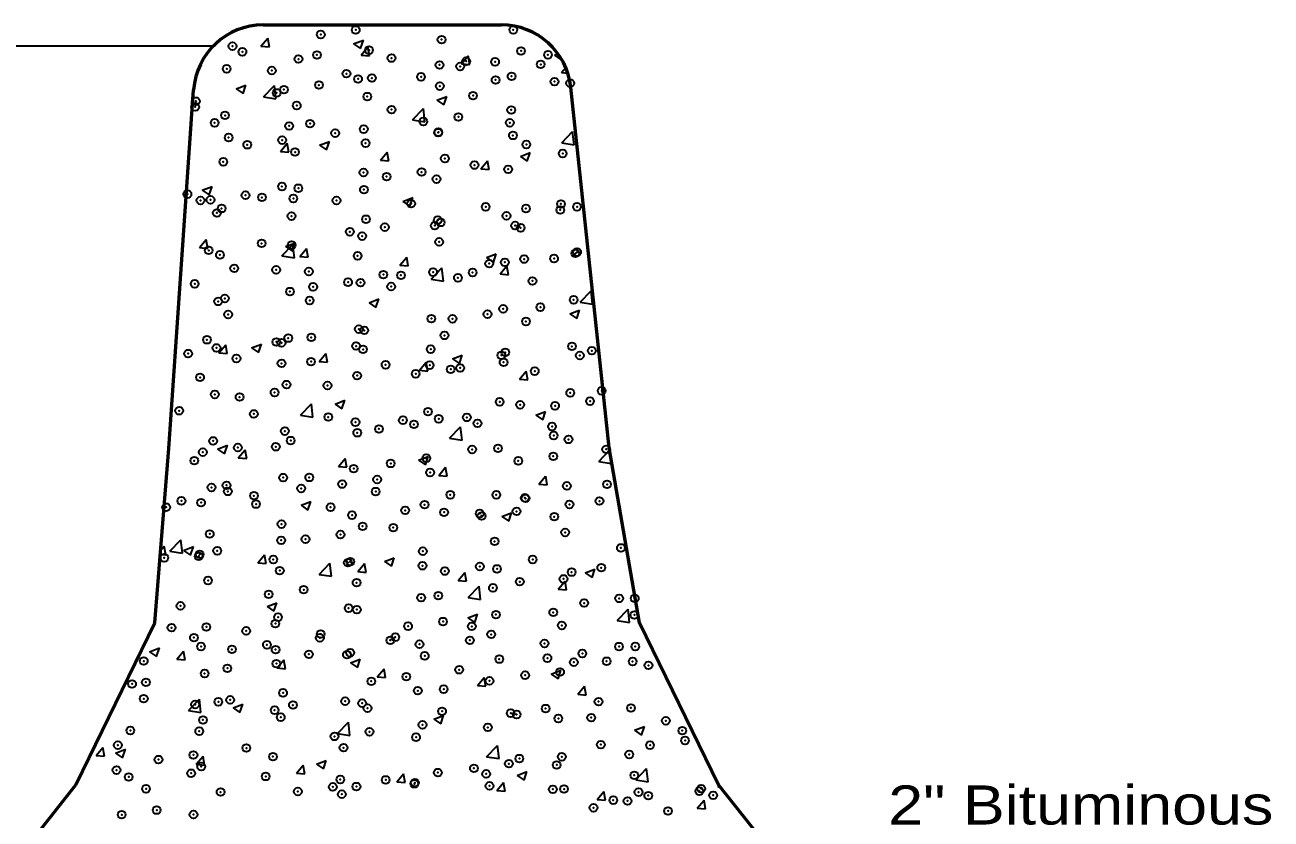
# Model space of a CAD drawing. Extents: x 14 to 49.3, y 28 to 50.
# Drawn here: x 34.953 to 39.413, y 38.182 to 41.024 of the extents above; entities that cross this region are included whole.
import ezdxf

# ---------------------------------------------------------------- set-up
doc = ezdxf.new("R2010")
doc.units = 0
doc.header["$LTSCALE"] = 0.056
doc.header["$PDMODE"] = 32
doc.header["$PDSIZE"] = 0.028
for name, color, linetype, lineweight in [('1', 7, 'Continuous', 35), ('3', 7, 'Continuous', 13), ('6', 7, 'Continuous', 13)]:
    doc.layers.add(name, color=color, linetype=linetype, lineweight=lineweight)

msp = doc.modelspace()

# ---------------------------------------------------------------- linework, layer by layer
at = {"layer": '1', "lineweight": 53}
for p, q in [((35.80625, 41.02392), (36.65817, 41.02392)), ((35.46842, 39.50783), (35.55683, 40.79108)), ((35.41742, 38.88442), (35.46842, 39.50783)), ((35.13542, 38.30408), (35.41742, 38.88442)), ((34.53892, 37.553), (35.13542, 38.30408))]:
    msp.add_line(p, q, dxfattribs=at)
at = {"layer": '1'}
for p, q in [((35.63342, 40.94792), (32.45458, 40.94792)), ((35.79783, 40.94767), (35.82192, 40.97633)), ((35.79783, 40.94767), (35.82775, 40.945)), ((35.82775, 40.945), (35.82192, 40.97633)), ((36.12933, 40.95617), (36.16433, 40.96967)), ((36.12933, 40.95617), (36.15417, 40.93942)), ((36.15417, 40.93942), (36.16433, 40.96958)), ((36.1565, 40.91625), (36.18058, 40.945)), ((36.18633, 40.91358), (36.18058, 40.945)), ((36.1565, 40.91625), (36.18633, 40.91367)), ((36.51508, 40.88483), (36.53917, 40.91358)), ((36.545, 40.88225), (36.53925, 40.91358)), ((36.84783, 40.91617), (36.86033, 40.92092)), ((36.84783, 40.91617), (36.87275, 40.89942)), ((36.87275, 40.89933), (36.87333, 40.90117)), ((36.51508, 40.88483), (36.545, 40.88225)), ((36.87375, 40.8535), (36.8885, 40.87108)), ((36.87375, 40.8535), (36.89575, 40.85158)), ((35.70917, 40.79492), (35.74417, 40.80833)), ((35.70917, 40.79492), (35.73408, 40.77817)), ((35.73408, 40.77817), (35.74417, 40.80833)), ((35.80675, 40.76692), (35.84567, 40.8075)), ((35.80675, 40.76692), (35.85117, 40.76)), ((35.85125, 40.76), (35.84567, 40.8075)), ((36.42775, 40.75492), (36.46275, 40.76833)), ((36.45267, 40.73808), (36.46275, 40.76833)), ((36.34033, 40.68417), (36.37933, 40.72475)), ((36.38483, 40.67725), (36.37933, 40.72475)), ((36.42775, 40.75492), (36.45258, 40.73808)), ((36.34033, 40.68417), (36.38483, 40.67725)), ((36.874, 40.60142), (36.91292, 40.642)), ((36.91842, 40.5945), (36.91292, 40.642)), ((35.86725, 40.5715), (35.89133, 40.60025)), ((35.89708, 40.56892), (35.89133, 40.60025)), ((36.00767, 40.59358), (36.04267, 40.60708)), ((36.00767, 40.59358), (36.0325, 40.57683)), ((36.0325, 40.57683), (36.04267, 40.60708)), ((36.874, 40.60142), (36.91842, 40.5945)), ((35.86725, 40.5715), (35.89708, 40.56892)), ((36.22583, 40.54017), (36.24992, 40.56892)), ((36.25575, 40.5375), (36.24992, 40.56883)), ((36.72617, 40.55358), (36.76125, 40.567)), ((36.72617, 40.55358), (36.75108, 40.53683)), ((36.75108, 40.53675), (36.76125, 40.567)), ((36.22583, 40.54017), (36.25575, 40.5375)), ((36.5845, 40.50875), (36.60858, 40.5375)), ((36.5845, 40.50875), (36.61433, 40.50617)), ((36.61433, 40.50617), (36.60858, 40.5375)), ((35.5875, 40.43233), (35.6225, 40.44583)), ((35.5875, 40.43233), (35.61242, 40.41558)), ((35.61242, 40.41558), (35.62258, 40.44575)), ((36.30608, 40.39233), (36.34108, 40.40575)), ((36.30608, 40.39233), (36.331, 40.3755)), ((36.331, 40.3755), (36.34108, 40.40575)), ((35.57792, 40.22683), (35.60208, 40.2555)), ((35.60783, 40.22417), (35.60208, 40.2555)), ((35.873, 40.19708), (35.912, 40.23767)), ((35.886, 40.23108), (35.921, 40.2445)), ((35.886, 40.23108), (35.91083, 40.21425)), ((35.91083, 40.21425), (35.921, 40.2445)), ((35.9175, 40.19017), (35.912, 40.23767)), ((35.57792, 40.22683), (35.60783, 40.22417)), ((35.873, 40.19708), (35.9175, 40.19017)), ((35.93658, 40.19542), (35.96067, 40.22417)), ((35.93658, 40.19542), (35.9665, 40.19283)), ((35.9665, 40.19283), (35.96067, 40.22417)), ((36.29525, 40.16408), (36.31933, 40.19275)), ((36.32508, 40.16142), (36.31933, 40.19275)), ((36.60458, 40.191), (36.63958, 40.20442)), ((36.60458, 40.191), (36.62942, 40.17425)), ((36.62942, 40.17417), (36.63958, 40.20442)), ((36.29525, 40.16408), (36.32508, 40.16142)), ((36.40667, 40.11433), (36.44558, 40.15492)), ((36.45108, 40.10742), (36.44558, 40.15492)), ((36.65383, 40.13267), (36.67792, 40.16142)), ((36.68375, 40.13008), (36.678, 40.16142)), ((36.40667, 40.11433), (36.45108, 40.10742)), ((36.65383, 40.13267), (36.68375, 40.13008)), ((36.94025, 40.03158), (36.97917, 40.07217)), ((36.98475, 40.02467), (36.97925, 40.07217)), ((36.18442, 40.02975), (36.21942, 40.04317)), ((36.18442, 40.02975), (36.20933, 40.013)), ((36.20933, 40.01292), (36.21942, 40.04317)), ((36.94025, 40.03158), (36.98475, 40.02467)), ((36.903, 39.98967), (36.938, 40.00317)), ((36.903, 39.98967), (36.92783, 39.97292)), ((36.92792, 39.97292), (36.938, 40.00308)), ((35.64733, 39.85075), (35.67142, 39.87942)), ((35.67725, 39.84808), (35.67142, 39.87942)), ((35.76433, 39.8685), (35.79933, 39.88192)), ((35.78917, 39.85167), (35.79933, 39.88192)), ((35.64733, 39.85075), (35.67725, 39.84808)), ((35.76433, 39.8685), (35.78917, 39.85167)), ((36.006, 39.81933), (36.03008, 39.84808)), ((36.03583, 39.81667), (36.03008, 39.84808)), ((36.48292, 39.82842), (36.51792, 39.84183)), ((36.50775, 39.81167), (36.51792, 39.84183)), ((36.006, 39.81933), (36.03583, 39.81675)), ((36.36458, 39.788), (36.38867, 39.81667)), ((36.36458, 39.788), (36.3945, 39.78533)), ((36.3945, 39.78533), (36.38867, 39.81667)), ((36.48292, 39.82842), (36.50775, 39.81167)), ((36.72325, 39.75658), (36.74733, 39.78533)), ((36.75308, 39.75392), (36.74733, 39.78533)), ((36.72325, 39.75658), (36.75308, 39.754)), ((35.93933, 39.62725), (35.97825, 39.66783)), ((35.98375, 39.62033), (35.97825, 39.66783)), ((36.06275, 39.66717), (36.09775, 39.68058)), ((36.06275, 39.66717), (36.08767, 39.65042)), ((36.08767, 39.65033), (36.09783, 39.68058)), ((35.93933, 39.62725), (35.98375, 39.62042)), ((36.78133, 39.62708), (36.81633, 39.64058)), ((36.78133, 39.62708), (36.80625, 39.61033)), ((36.80625, 39.61033), (36.81633, 39.6405)), ((36.47292, 39.5445), (36.51192, 39.58508)), ((36.51742, 39.53758), (36.51192, 39.58508)), ((36.51742, 39.53758), (36.51192, 39.58508)), ((35.64267, 39.50592), (35.67767, 39.51933)), ((35.66758, 39.48908), (35.67767, 39.51933)), ((36.47292, 39.5445), (36.51742, 39.53758)), ((35.64267, 39.50592), (35.6675, 39.48908)), ((35.71667, 39.47458), (35.74083, 39.50333)), ((35.71667, 39.47458), (35.74658, 39.472)), ((35.74658, 39.472), (35.74083, 39.50333)), ((36.36125, 39.46583), (36.39625, 39.47925)), ((36.38608, 39.44908), (36.39625, 39.47925)), ((37.00658, 39.46175), (37.0455, 39.50233)), ((37.051, 39.45483), (37.0455, 39.50233)), ((36.07533, 39.44325), (36.09942, 39.472)), ((36.07533, 39.44325), (36.10525, 39.44067)), ((36.07533, 39.44325), (36.10525, 39.44067)), ((36.10525, 39.44058), (36.09942, 39.47192)), ((36.36125, 39.46583), (36.38608, 39.44908)), ((36.434, 39.41183), (36.45808, 39.44058)), ((36.46383, 39.40925), (36.45808, 39.44058)), ((37.00658, 39.46175), (37.051, 39.45483)), ((36.434, 39.41183), (36.46383, 39.40925)), ((36.79258, 39.3805), (36.81667, 39.40925)), ((36.8225, 39.37783), (36.81675, 39.40917)), ((36.8225, 39.37783), (36.81675, 39.40917)), ((36.79258, 39.3805), (36.8225, 39.37783)), ((35.94108, 39.30458), (35.97617, 39.318)), ((35.94108, 39.30458), (35.966, 39.28783)), ((35.966, 39.28783), (35.97617, 39.318)), ((36.65967, 39.26458), (36.69467, 39.278)), ((36.65967, 39.26458), (36.68458, 39.24775)), ((36.68458, 39.24775), (36.69467, 39.278)), ((35.472, 39.14025), (35.51092, 39.18083)), ((35.51642, 39.13333), (35.51092, 39.18083)), ((35.43742, 39.129), (35.45733, 39.12725)), ((35.43858, 39.14317), (35.45158, 39.15858)), ((35.45733, 39.12725), (35.45158, 39.15858)), ((35.472, 39.14025), (35.51642, 39.13333)), ((35.521, 39.14333), (35.556, 39.15675)), ((35.521, 39.14333), (35.54592, 39.12658)), ((35.54592, 39.1265), (35.556, 39.15675)), ((35.78608, 39.0985), (35.81017, 39.12725)), ((35.816, 39.09592), (35.81017, 39.12725)), ((36.23958, 39.10325), (36.27458, 39.11675)), ((36.26442, 39.0865), (36.27458, 39.11667)), ((35.78608, 39.0985), (35.816, 39.09592)), ((36.00558, 39.0575), (36.04458, 39.09808)), ((36.05008, 39.05058), (36.04458, 39.098)), ((36.14475, 39.06717), (36.16883, 39.09583)), ((36.17458, 39.0645), (36.16883, 39.09583)), ((36.23958, 39.10325), (36.26442, 39.0865)), ((36.95817, 39.06325), (36.99317, 39.07667)), ((36.983, 39.04642), (36.99317, 39.07667)), ((36.00558, 39.0575), (36.05008, 39.05058)), ((36.14475, 39.06717), (36.17458, 39.0645)), ((36.50333, 39.03575), (36.52742, 39.0645)), ((36.50333, 39.03575), (36.53325, 39.03317)), ((36.53325, 39.03317), (36.52742, 39.0645)), ((36.862, 39.00442), (36.88608, 39.03308)), ((36.89183, 39.00175), (36.88608, 39.03308)), ((36.95817, 39.06325), (36.983, 39.04642)), ((36.53925, 38.97467), (36.57817, 39.01525)), ((36.58367, 38.96775), (36.57817, 39.01525)), ((36.862, 39.00442), (36.89183, 39.00175)), ((35.8195, 38.942), (35.8545, 38.95542)), ((35.8195, 38.942), (35.84433, 38.92525)), ((35.84433, 38.92525), (35.8545, 38.95542)), ((36.53925, 38.97467), (36.58367, 38.96783)), ((36.538, 38.902), (36.573, 38.91542)), ((36.538, 38.902), (36.56292, 38.88517)), ((36.56292, 38.88517), (36.57308, 38.91542)), ((37.07283, 38.89192), (37.11175, 38.9325)), ((37.11733, 38.885), (37.11183, 38.9325)), ((37.07283, 38.89192), (37.11733, 38.88508)), ((35.39933, 38.78075), (35.43433, 38.79417)), ((35.39933, 38.78075), (35.42425, 38.764)), ((35.39933, 38.78075), (35.42425, 38.764)), ((35.42425, 38.76392), (35.43433, 38.79417)), ((35.49683, 38.75383), (35.52092, 38.7825)), ((35.52675, 38.75117), (35.52092, 38.7825)), ((35.49683, 38.75383), (35.52675, 38.75117)), ((35.85542, 38.72242), (35.87958, 38.75117)), ((35.85542, 38.72242), (35.88533, 38.71983)), ((35.88533, 38.71983), (35.87958, 38.75117)), ((36.11792, 38.74067), (36.15292, 38.75417)), ((36.11792, 38.74067), (36.14275, 38.72392)), ((36.14283, 38.72392), (36.15292, 38.75408)), ((36.21408, 38.69108), (36.23817, 38.71975)), ((36.244, 38.68842), (36.23817, 38.71975)), ((36.8365, 38.70067), (36.8715, 38.71408)), ((36.86133, 38.68383), (36.8715, 38.71408)), ((36.21408, 38.69108), (36.244, 38.68842)), ((36.57275, 38.65967), (36.59683, 38.68842)), ((36.60258, 38.657), (36.59683, 38.68842)), ((36.8365, 38.70067), (36.86133, 38.68392)), ((36.57275, 38.65967), (36.60258, 38.65708)), ((36.93133, 38.62833), (36.95542, 38.657)), ((36.93133, 38.62833), (36.96125, 38.62567)), ((36.96125, 38.62567), (36.9555, 38.657)), ((35.53825, 38.57042), (35.57725, 38.611)), ((35.58275, 38.5635), (35.57725, 38.611)), ((35.69783, 38.57942), (35.73283, 38.59283)), ((35.72267, 38.56267), (35.73283, 38.59283)), ((37.29, 38.59692), (37.29167, 38.59892)), ((37.29, 38.59692), (37.29275, 38.59667)), ((35.53825, 38.57042), (35.58275, 38.5635)), ((35.69783, 38.57942), (35.72267, 38.56267)), ((36.41633, 38.53942), (36.45142, 38.55283)), ((36.41633, 38.53942), (36.44125, 38.52258)), ((36.44125, 38.52258), (36.45142, 38.55283)), ((36.07192, 38.48767), (36.11083, 38.52825)), ((36.11633, 38.48075), (36.11083, 38.52825)), ((37.13492, 38.49933), (37.16992, 38.51275)), ((37.13492, 38.49933), (37.15983, 38.48258)), ((37.15983, 38.48258), (37.16992, 38.51275)), ((36.07192, 38.48767), (36.11633, 38.48075)), ((35.20758, 38.40908), (35.23167, 38.43783)), ((35.20758, 38.40908), (35.2375, 38.4065)), ((35.2375, 38.40642), (35.23167, 38.43775)), ((35.27767, 38.41817), (35.31267, 38.43158)), ((35.27767, 38.41817), (35.30258, 38.40142)), ((35.30258, 38.40142), (35.31275, 38.43158)), ((35.56617, 38.37767), (35.59033, 38.40642)), ((35.59608, 38.37508), (35.59033, 38.40642)), ((36.6055, 38.40492), (36.64442, 38.4455)), ((36.6055, 38.40492), (36.65, 38.398)), ((36.65, 38.398), (36.6445, 38.44542)), ((35.56617, 38.37767), (35.59608, 38.37508)), ((35.92483, 38.34633), (35.94892, 38.37508)), ((35.95475, 38.34367), (35.94892, 38.375)), ((35.99625, 38.37817), (36.03125, 38.39158)), ((35.99625, 38.37817), (36.02117, 38.36133)), ((36.02117, 38.36133), (36.03125, 38.39158)), ((37.13917, 38.32208), (37.17808, 38.36275)), ((37.18358, 38.31525), (37.17808, 38.36267)), ((35.92483, 38.34633), (35.95475, 38.34375)), ((36.2835, 38.31492), (36.30758, 38.34367)), ((36.2835, 38.31492), (36.31333, 38.31233)), ((36.31333, 38.31233), (36.30758, 38.34367)), ((36.71483, 38.33808), (36.74983, 38.3515)), ((36.71483, 38.33808), (36.73967, 38.32133)), ((36.73967, 38.32125), (36.74983, 38.3515)), ((37.13917, 38.32208), (37.18358, 38.31525)), ((36.64208, 38.28358), (36.66617, 38.31233)), ((36.64208, 38.28358), (36.672, 38.281)), ((36.672, 38.28092), (36.66617, 38.31225)), ((37.00075, 38.25217), (37.02483, 38.28092)), ((37.03058, 38.24958), (37.02483, 38.28092)), ((37.43342, 38.298), (37.43825, 38.29992)), ((37.43342, 38.298), (37.447, 38.28883)), ((37.00075, 38.25217), (37.03058, 38.24958)), ((37.35933, 38.22083), (37.38342, 38.24958)), ((37.38925, 38.21817), (37.3835, 38.2495)), ((37.35933, 38.22083), (37.38925, 38.21825))]:
    msp.add_line(p, q, dxfattribs=at)
at = {"layer": '1', "lineweight": 53}
msp.add_lwpolyline([(38.0315, 37.553), (37.43492, 38.30408), (37.15292, 38.88442), (37.04442, 39.51033), (36.90675, 40.80042)], dxfattribs=at)
for centre, start, end in [((35.80625, 40.77392), 90, 176.0601), ((36.65817, 40.77392), 6.09322, 90)]:
    msp.add_arc(centre, 0.25, start, end, dxfattribs=at)
at = {"layer": '1'}
for p in [(36.01175, 40.9895), (36.13692, 41.006), (36.70083, 41.0065), (35.69592, 40.94792), (36.18442, 40.93383), (36.44417, 40.97133), (36.7285, 40.93075), (35.73133, 40.92783), (35.93192, 40.90183), (35.99825, 40.9165), (36.26517, 40.90525), (36.532, 40.894), (36.63567, 40.89175), (36.825, 40.91675), (35.67517, 40.86658), (35.83675, 40.86067), (36.10367, 40.84933), (36.43692, 40.88067), (36.5105, 40.87533), (36.79892, 40.88267), (36.00533, 40.80883), (36.14533, 40.83058), (36.19475, 40.83375), (36.37058, 40.83808), (36.43808, 40.80492), (36.6375, 40.82683), (36.69475, 40.84008), (36.84833, 40.82092), (36.90433, 40.8155), (35.85375, 40.78058), (35.88017, 40.79233), (36.17833, 40.76742), (36.55675, 40.77092), (35.56217, 40.7305), (35.56442, 40.75075), (35.92583, 40.73542), (36.26517, 40.72083), (36.6935, 40.7195), (35.63183, 40.67367), (35.66908, 40.70017), (35.97358, 40.67075), (36.379, 40.67808), (36.50417, 40.69458), (36.68867, 40.67367), (35.682, 40.62075), (35.89875, 40.66233), (36.06317, 40.6365), (36.16567, 40.65108), (36.432, 40.63842), (36.43258, 40.63983), (36.6995, 40.6285), (35.74867, 40.59508), (35.87383, 40.61158), (36.17225, 40.60092), (36.74767, 40.59592), (35.663, 40.53375), (35.91975, 40.56892), (36.45608, 40.54583), (36.87775, 40.56383), (36.1645, 40.49583), (36.37258, 40.49733), (36.562, 40.52233), (36.68258, 40.50717), (35.87292, 40.44575), (36.24742, 40.48092), (36.42592, 40.472), (35.5345, 40.41817), (35.58133, 40.39567), (35.61708, 40.39792), (35.74225, 40.41442), (35.80133, 40.40683), (35.91367, 40.4025), (35.93167, 40.43933), (36.06825, 40.39558), (36.16625, 40.4345), (35.63992, 40.351), (35.65692, 40.36725), (36.33517, 40.38433), (36.60208, 40.373), (36.74617, 40.36667), (36.869, 40.36175), (36.87142, 40.38317), (36.92908, 40.37275), (35.90683, 40.33967), (36.17367, 40.32842), (36.43042, 40.32508), (36.44058, 40.31717), (36.67658, 40.34075), (36.7075, 40.30583), (36.11592, 40.28367), (36.16017, 40.26808), (36.24108, 40.30017), (36.41983, 40.3055), (36.72708, 40.29758), (35.61075, 40.21717), (35.80008, 40.24208), (35.90758, 40.236), (36.4355, 40.2475), (35.65083, 40.20083), (36.14383, 40.1975), (36.6705, 40.17433), (36.73983, 40.18592), (36.84683, 40.18783), (36.923, 40.20633), (36.92917, 40.21083), (35.70192, 40.15275), (35.85225, 40.14742), (35.96883, 40.14142), (36.23575, 40.13017), (36.29892, 40.12792), (36.41375, 40.13908), (36.55525, 40.13775), (36.61467, 40.1695), (35.56067, 40.09733), (35.98433, 40.0865), (36.1095, 40.103), (36.15408, 40.10158), (36.26367, 40.08767), (36.50267, 40.11892), (36.7695, 40.10758), (35.66858, 40.04492), (35.9015, 40.06958), (36.91692, 40.03983), (35.64475, 40.03442), (35.97208, 40.03767), (36.66442, 40.00783), (36.79767, 40.01367), (35.6805, 39.98758), (36.40767, 39.97267), (36.48317, 39.97225), (36.60833, 39.98875), (36.74625, 39.96275), (35.978, 39.90575), (36.148, 39.93517), (36.16733, 39.93067), (36.45467, 39.91275), (35.6045, 39.89725), (35.63867, 39.86792), (35.85283, 39.88925), (35.87142, 39.88592), (35.89542, 39.90317), (36.13833, 39.87467), (36.163, 39.86267), (36.40525, 39.86342), (36.91083, 39.87342), (35.53708, 39.84767), (35.70992, 39.83008), (35.97683, 39.81875), (36.65833, 39.84142), (36.66617, 39.8165), (36.67217, 39.85208), (36.93908, 39.84083), (36.98192, 39.858), (35.87142, 39.81258), (36.24375, 39.8075), (36.35158, 39.77508), (36.40158, 39.80617), (36.47675, 39.7915), (36.51067, 39.79625), (36.77758, 39.78492), (35.57983, 39.76258), (35.88933, 39.73667), (36.03583, 39.7335), (36.14192, 39.76875), (35.63258, 39.7015), (35.72125, 39.69208), (35.8465, 39.70858), (36.90475, 39.707), (37.01717, 39.7145), (35.50508, 39.64308), (36.3955, 39.63975), (36.65225, 39.67492), (36.72558, 39.66442), (36.85042, 39.66083), (36.97558, 39.67733), (35.772, 39.63175), (36.03883, 39.6205), (36.13583, 39.60225), (36.30575, 39.60925), (36.34525, 39.59433), (36.434, 39.61442), (36.53458, 39.61925), (36.57267, 39.59792), (35.88325, 39.57025), (36.14242, 39.56433), (36.22008, 39.57783), (36.83958, 39.58667), (36.84542, 39.55467), (35.6265, 39.53508), (35.71492, 39.51133), (35.85083, 39.51425), (35.90425, 39.53625), (36.55383, 39.50458), (36.64617, 39.5085), (36.89867, 39.5405), (37.03342, 39.505), (35.55925, 39.46425), (35.58975, 39.49483), (36.38942, 39.47333), (36.71883, 39.46358), (36.844, 39.48008), (36.12975, 39.43583), (36.26217, 39.45458), (36.40308, 39.42208), (35.67458, 39.37625), (35.87717, 39.40383), (35.97058, 39.4045), (36.0885, 39.38067), (36.21367, 39.39708), (36.89258, 39.37408), (37.03633, 39.37967), (35.6205, 39.36858), (35.679, 39.35442), (35.77275, 39.33908), (35.9415, 39.365), (36.20842, 39.35375), (36.47533, 39.34242), (36.64008, 39.34208), (36.74225, 39.33117), (36.74475, 39.32958), (35.45825, 39.29767), (35.51308, 39.32042), (35.58342, 39.31417), (35.78, 39.30908), (36.04692, 39.29783), (36.31383, 39.28658), (36.38333, 39.30683), (36.7125, 39.28292), (36.90183, 39.30783), (37.00917, 39.31992), (35.87108, 39.23733), (36.12367, 39.26933), (36.45317, 39.27958), (36.58075, 39.27525), (36.58733, 39.26642), (36.84767, 39.264), (35.61442, 39.20217), (36.08217, 39.19992), (36.16158, 39.2295), (36.2715, 39.22483), (36.8865, 39.20758), (35.87, 39.1795), (35.957, 39.18342), (36.634, 39.17558), (37.08608, 39.15217), (35.45183, 39.11692), (35.57508, 39.12217), (35.57842, 39.12942), (35.64125, 39.14183), (35.842, 39.11083), (36.11758, 39.10292), (36.37725, 39.14042), (36.77033, 39.11058), (35.865, 39.07092), (36.10892, 39.09958), (36.37583, 39.08833), (36.45575, 39.06925), (36.58092, 39.08567), (36.64275, 39.077), (36.90967, 39.06575), (37.01567, 39.08133), (35.60833, 39.03567), (36.14, 39.02767), (36.72408, 39.03133), (36.88042, 39.04117), (35.8255, 38.98625), (35.95067, 39.00267), (36.37117, 38.974), (36.4325, 38.98125), (36.62792, 39.00917), (37.07975, 38.9715), (37.1355, 38.97158), (35.50967, 38.94467), (36.1115, 38.9365), (36.14092, 38.93117), (36.95458, 38.955), (35.84933, 38.88117), (35.85892, 38.9045), (36.44942, 38.8885), (36.63875, 38.91342), (36.84392, 38.9215), (37.13408, 38.91225), (35.47775, 38.86667), (35.60225, 38.86925), (35.74467, 38.85533), (36.01158, 38.84408), (36.32425, 38.872), (36.55233, 38.87142), (36.62183, 38.84275), (36.87442, 38.87475), (35.55775, 38.83108), (35.58317, 38.7995), (35.81908, 38.8055), (36.0085, 38.83042), (36.26075, 38.82142), (36.2785, 38.83283), (36.36508, 38.8075), (36.54542, 38.8215), (36.81233, 38.81025), (37.07925, 38.799), (37.13758, 38.79917), (35.37817, 38.74742), (35.69392, 38.789), (35.85008, 38.78817), (35.96917, 38.77133), (36.10542, 38.77), (36.117, 38.77692), (36.38392, 38.76567), (36.65083, 38.75433), (36.823, 38.75775), (36.94817, 38.77425), (37.03483, 38.7465), (37.128, 38.74575), (35.59617, 38.70283), (35.67758, 38.72133), (35.85283, 38.738), (36.50725, 38.71617), (36.86833, 38.70825), (36.91775, 38.74308), (37.18467, 38.73183), (35.33642, 38.66533), (35.38592, 38.67125), (36.19267, 38.67483), (36.31783, 38.69125), (36.61575, 38.67625), (36.74325, 38.6965), (35.37825, 38.6125), (35.87692, 38.63325), (36.359, 38.64108), (36.45167, 38.64642), (35.56242, 38.59183), (35.64517, 38.60117), (35.68758, 38.60833), (35.84675, 38.57158), (35.91208, 38.58992), (36.09933, 38.60358), (36.16008, 38.59633), (36.179, 38.57867), (36.44592, 38.56733), (36.81667, 38.57708), (37.006, 38.602), (37.12192, 38.57933), (35.59008, 38.53633), (35.8685, 38.54633), (36.6915, 38.56058), (36.71283, 38.55608), (36.86225, 38.54183), (36.97975, 38.54483), (37.24667, 38.5335), (35.33033, 38.49892), (35.57692, 38.49625), (36.06117, 38.47758), (36.18633, 38.49408), (36.37567, 38.519), (36.60967, 38.50983), (37.30583, 38.49825), (35.28533, 38.44625), (35.74542, 38.436), (36.09325, 38.43717), (36.35292, 38.47458), (37.01425, 38.44817), (37.19025, 38.44633), (37.31542, 38.46283), (35.43083, 38.39458), (35.556, 38.41108), (35.84067, 38.40508), (36.72267, 38.39817), (36.8745, 38.40475), (37.11583, 38.41292), (35.28092, 38.357), (35.54783, 38.34567), (35.584, 38.36992), (36.431, 38.34808), (36.55992, 38.36333), (36.60358, 38.34342), (36.68508, 38.37983), (36.85617, 38.37542), (35.32425, 38.33242), (35.81475, 38.33442), (36.08167, 38.32317), (36.24417, 38.32183), (36.34683, 38.30817), (36.34858, 38.31183), (36.6155, 38.30058), (37.134, 38.33842), (35.38633, 38.28983), (35.65325, 38.2785), (35.92967, 38.28042), (36.05483, 38.29683), (36.08717, 38.27067), (36.13942, 38.298), (36.84242, 38.28833), (36.88242, 38.28933), (37.14925, 38.278), (37.18392, 38.26558), (37.3665, 38.28167), (37.37325, 38.29058), (37.41617, 38.26675), (35.4245, 38.21392), (36.98783, 38.22217), (37.05875, 38.24917), (37.10975, 38.24642), (37.25475, 38.21083), (35.29933, 38.19742), (35.55625, 38.19792)]:
    msp.add_point(p, dxfattribs=at)
at = {"layer": '6'}
msp.add_line((35.69592, 40.94792), (35.696, 40.94792), dxfattribs=at)

# ---------------------------------------------------------------- texts
at = {"layer": '3', "width": 1.2}
msp.add_text('2" Bituminous', height=0.14, dxfattribs=at).set_placement((38.04275, 38.16217))

doc.saveas('drawing.dxf')
